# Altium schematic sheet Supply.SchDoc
size A4; CheckedBy: Everyone how cares; DocumentNumber: 2; SheetNumber: 2; SheetTotal: 4
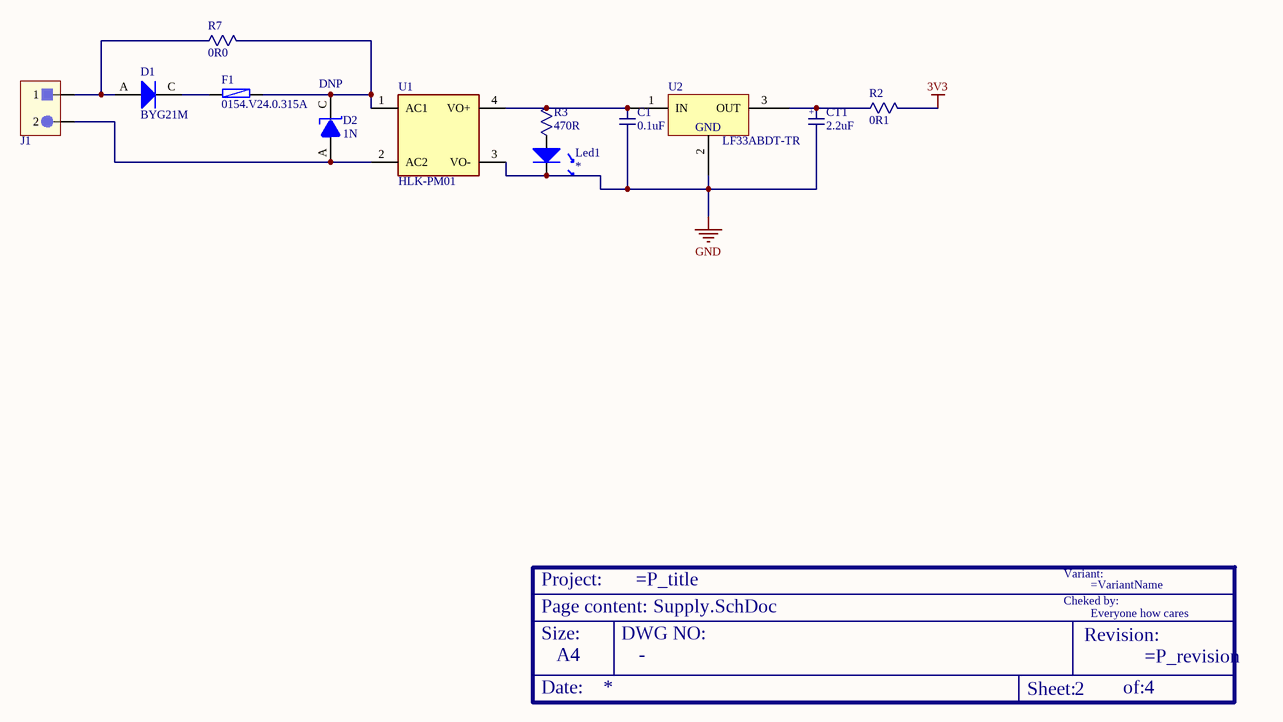
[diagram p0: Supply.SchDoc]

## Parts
?  Size: A4  (hidden comment: TitleBox)  (graphical)
C1  value 0.1uF  [0603C]  (hidden comment: Ceramic Capacitor)
CT1  value 2.2uF  [1206T]  (hidden comment: Tantalum capacitor)
D1  value BYG21M  [DO-214AC]  (hidden comment: DNP)
D2  DNP  value 1N  [1N5359BG]
F1  value 0154.V24.0.315A  [Fuseholder154]  (hidden comment: DNP)
J1  Conector  [691313510002]  (value not drawn)
Led1  Led  [LED_5MM_RED_1C-2A]  (value not drawn)
R2  value 0R1  [0603]  (hidden comment: Res)
R3  value 470R  [0603]  (hidden comment: Res)
R7  value 0R0  [0805]  (hidden comment: Res)
U1  HLK-PM01  [HLK-PM01/ISE]
U2  value LF33ABDT-TR  [DPAK-TO-252-3, CASE369C]  (hidden comment: LDO)

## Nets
3V3: R2.2
GND: C1.2 CT1.2 Led1.C U1.3(VO-) U2.2(GND)
NetC1_1: C1.1 R3.2 U1.4(VO+) U2.1(IN)
NetCT1_1: CT1.1 R2.1 U2.3(OUT)
NetD1_A: D1.A J1.1 R7.1
NetD1_C: D1.C F1.1
NetD2_A: D2.A J1.2 U1.2(AC2)
NetD2_C: D2.C F1.2 R7.2 U1.1(AC1)
NetLed1_A: Led1.A R3.1

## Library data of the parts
? = TitleBox_1: coordenadas: (610;20) Size A4
C1 = CC
CT1 = CT: Condensador Tantalum
D1 = Diode: notas: 24Vin
D2 = Zener Diode
F1 = Fusivel_LITTELFUSE_0154: Fusivel SMD LITTELFUSE  0154; notas: 24Vin
J1 = Conector 2 pins
R7 = Res: notas: AC
U1 = HLK-PM01: HI-LINK Ultra-compact power module HLK-PM01<p> <ul> <li>Meet UL, CE requirements</li> <li>Ultra-thin, ultra-small</li> <li>All voltage input (AC: 90 ~ 264V)</li> <li>Low ripple and low noise</li> <li>Output overload and short circuit protection</li> <li>High efficiency, high power density</li> <li>The product is designed to meet the requirements of EMC and Safety Test</li> <li>Low power consumption, environmental protection, no-load loss <0.1W</li> <li>100% load aging and testing</li>
U2 = LF33ABDT-TR: ST, LF33ABDT-TR, Fixed LDO Voltage Regulator, 3V to 16V, 400mV Dropout, 3.3Vout, 0.5Aout, TO-252-3; Manufacturer: STMICROELECTRONICS; Input Voltage Min: 3; Input Voltage Max: 16; Output Voltage Nom.: 3.3; Output Current: 0.5; Dropout Voltage Vdo: 400; LDO Regulator Case Style: TO-252; SVHC: No SVHC (15-Jun-2015); Accuracy %: 1%; Base Number: 33; No. of Outputs: 1; Operating Voltage Tolerance +: 2%; Primary Input Voltage: 5.3; Supply Voltage Min: 4.3; Voltage Regulator Type: Fixed<!--FANDB--><div class="features-and-benefits-container"><div class="features-and-benefits-description"><span class="features-benefits-value">The LF33ABDT-TR is a Low-drop Voltage Regulator with inhibit function and 3.3V output voltage. Low quiescent current make it particularly suitable for low-noise, low power applications and especially in battery powered systems. In the 5-pin configuration (PPAK) a shutdown logic control function is available (pin 2, TTL compatible). This means that when the device is used as a local regulator, a part of the board can be put in standby, decreasing the total power consumption. In the 3-terminal configuration, the device has the same electrical performance, but it is fixed in ON state. It requires a capacitor of only 2.2µF for stability, saving board space and costs.</span></div><div class="features-and-benefits-list"><ul class="features-and-benefits-list-list"><li class="features-and-benefits-list-item">Very low drop-out voltage (0.45V)</li><li class="features-and-benefits-list-item">Very low quiescent current (typical 50µA in OFF mode, 500µA in ON mode)</li><li class="features-and-benefits-list-item">500mA Output current</li><li class="features-and-benefits-list-item">Logic-controlled electronic shutdown</li><li class="features-and-benefits-list-item">Internal current and thermal limit</li><li class="features-and-benefits-list-item">Available in ±1% (AB) or ±2% (C) selection at 25°C</li><li class="features-and-benefits-list-item">80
